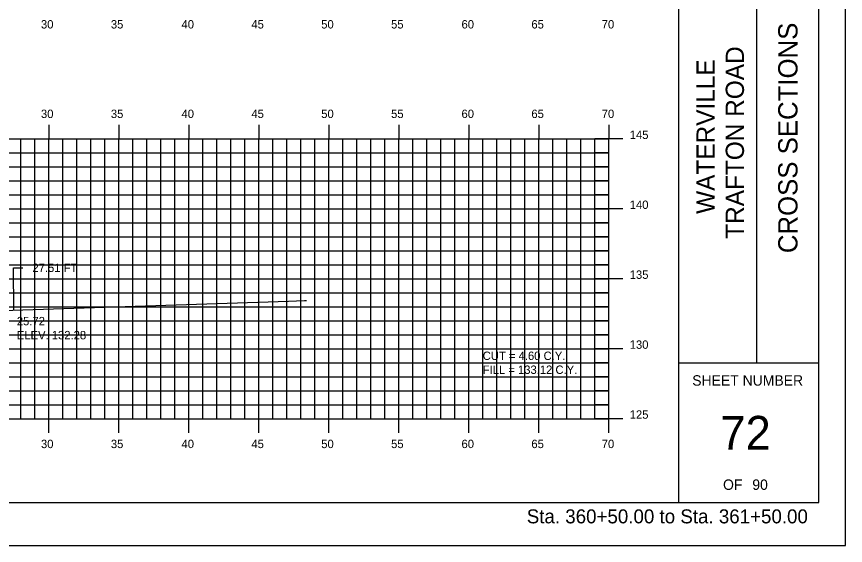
# Model space of a CAD drawing. Extents: x 1146525 to 1146695, y 608981 to 609091.
# Drawn here: x 1146635.4 to 1146694.6, y 608981.3 to 609019.1 of the extents above; entities that cross this region are included whole.
import ezdxf

# ---------------------------------------------------------------- set-up
doc = ezdxf.new("R2010")
doc.units = 0
for name, color, linetype in [('BORDER', 7, 'Continuous'), ('D_Text_Standard', 7, 'Continuous'), ('H_V ANNOTATION', 7, 'Continuous'), ('HIGHWAY_TITLE', 7, 'Continuous'), ('MAJOR', 7, 'Continuous'), ('MINOR', 7, 'Continuous'), ('PLOT BOUNDARY', 7, 'Continuous'), ('S_Roadway_Centerline', 7, 'Continuous')]:
    doc.layers.add(name, color=color, linetype=linetype)

msp = doc.modelspace()

# ---------------------------------------------------------------- linework, layer by layer
at = {"layer": 'BORDER'}
for p, q in [((1146682.671, 608984.335), (1146682.671, 609089.335)), ((1146688.262, 608994.338), (1146688.262, 609029.338)), ((1146682.671, 608994.338), (1146692.671, 608994.338))]:
    msp.add_line(p, q, dxfattribs=at)
msp.add_lwpolyline([(1146532.671, 608984.335), (1146692.671, 608984.335), (1146692.671, 609089.335), (1146532.671, 609089.335)], close=True, dxfattribs=at)
at = {"layer": 'D_Text_Standard'}
msp.add_lwpolyline([(1146635.18, 608998.09), (1146635.15, 609001.127), (1146635.83, 609001.127)], dxfattribs=at)
at = {"layer": 'MAJOR'}
for p, q in [((1146637.671, 609011.337), (1146637.671, 609010.335)), ((1146642.671, 609011.337), (1146642.671, 609010.335)), ((1146647.671, 609011.337), (1146647.671, 609010.335)), ((1146652.671, 609011.337), (1146652.671, 609010.335)), ((1146657.671, 609011.337), (1146657.671, 609010.335)), ((1146662.671, 609011.337), (1146662.671, 609010.335)), ((1146667.671, 609011.337), (1146667.671, 609010.335)), ((1146672.671, 609011.337), (1146672.671, 609010.335)), ((1146677.671, 609011.337), (1146677.671, 609010.335)), ((1146537.671, 609010.335), (1146677.671, 609010.335)), ((1146537.671, 609010.335), (1146677.671, 609010.335)), ((1146637.671, 608990.335), (1146637.671, 609010.335)), ((1146642.671, 608990.335), (1146642.671, 609010.335)), ((1146647.671, 608990.335), (1146647.671, 609010.335)), ((1146652.671, 608990.335), (1146652.671, 609010.335)), ((1146657.671, 608990.335), (1146657.671, 609010.335)), ((1146662.671, 608990.335), (1146662.671, 609010.335)), ((1146667.671, 608990.335), (1146667.671, 609010.335)), ((1146672.671, 608990.335), (1146672.671, 609010.335)), ((1146678.673, 609010.335), (1146676.669, 609010.335)), ((1146677.671, 608990.335), (1146677.671, 609010.335)), ((1146677.671, 608990.335), (1146677.671, 609010.335)), ((1146537.671, 609005.335), (1146677.671, 609005.335)), ((1146678.673, 609005.335), (1146676.669, 609005.335)), ((1146537.671, 609000.335), (1146677.671, 609000.335)), ((1146678.673, 609000.335), (1146676.669, 609000.335)), ((1146537.671, 608995.335), (1146677.671, 608995.335)), ((1146678.673, 608995.335), (1146676.669, 608995.335)), ((1146537.671, 608990.335), (1146677.671, 608990.335)), ((1146537.671, 608990.335), (1146677.671, 608990.335)), ((1146637.671, 608989.333), (1146637.671, 608990.335)), ((1146642.671, 608989.333), (1146642.671, 608990.335)), ((1146647.671, 608989.333), (1146647.671, 608990.335)), ((1146652.671, 608989.333), (1146652.671, 608990.335)), ((1146657.671, 608989.333), (1146657.671, 608990.335)), ((1146662.671, 608989.333), (1146662.671, 608990.335)), ((1146667.671, 608989.333), (1146667.671, 608990.335)), ((1146672.671, 608989.333), (1146672.671, 608990.335)), ((1146678.673, 608990.335), (1146676.669, 608990.335)), ((1146677.671, 608989.333), (1146677.671, 608990.335))]:
    msp.add_line(p, q, dxfattribs=at)
at = {"layer": 'MINOR'}
for p, q in [((1146635.671, 608990.335), (1146635.671, 609010.335)), ((1146636.671, 608990.335), (1146636.671, 609010.335)), ((1146638.671, 608990.335), (1146638.671, 609010.335)), ((1146639.671, 608990.335), (1146639.671, 609010.335)), ((1146640.671, 608990.335), (1146640.671, 609010.335)), ((1146641.671, 608990.335), (1146641.671, 609010.335)), ((1146643.671, 608990.335), (1146643.671, 609010.335)), ((1146644.671, 608990.335), (1146644.671, 609010.335)), ((1146645.671, 608990.335), (1146645.671, 609010.335)), ((1146646.671, 608990.335), (1146646.671, 609010.335)), ((1146648.671, 608990.335), (1146648.671, 609010.335)), ((1146649.671, 608990.335), (1146649.671, 609010.335)), ((1146650.671, 608990.335), (1146650.671, 609010.335)), ((1146651.671, 608990.335), (1146651.671, 609010.335)), ((1146653.671, 608990.335), (1146653.671, 609010.335)), ((1146654.671, 608990.335), (1146654.671, 609010.335)), ((1146655.671, 608990.335), (1146655.671, 609010.335)), ((1146656.671, 608990.335), (1146656.671, 609010.335)), ((1146658.671, 608990.335), (1146658.671, 609010.335)), ((1146659.671, 608990.335), (1146659.671, 609010.335)), ((1146660.671, 608990.335), (1146660.671, 609010.335)), ((1146661.671, 608990.335), (1146661.671, 609010.335)), ((1146663.671, 608990.335), (1146663.671, 609010.335)), ((1146664.671, 608990.335), (1146664.671, 609010.335)), ((1146665.671, 608990.335), (1146665.671, 609010.335)), ((1146666.671, 608990.335), (1146666.671, 609010.335)), ((1146668.671, 608990.335), (1146668.671, 609010.335)), ((1146669.671, 608990.335), (1146669.671, 609010.335)), ((1146670.671, 608990.335), (1146670.671, 609010.335)), ((1146671.671, 608990.335), (1146671.671, 609010.335)), ((1146673.671, 608990.335), (1146673.671, 609010.335)), ((1146674.671, 608990.335), (1146674.671, 609010.335)), ((1146675.671, 608990.335), (1146675.671, 609010.335)), ((1146676.671, 608990.335), (1146676.671, 609010.335)), ((1146537.671, 609009.335), (1146677.671, 609009.335)), ((1146677.671, 609009.335), (1146676.669, 609009.335)), ((1146537.671, 609008.335), (1146677.671, 609008.335)), ((1146677.671, 609008.335), (1146676.669, 609008.335)), ((1146537.671, 609007.335), (1146677.671, 609007.335)), ((1146677.671, 609007.335), (1146676.669, 609007.335)), ((1146537.671, 609006.335), (1146677.671, 609006.335)), ((1146677.671, 609006.335), (1146676.669, 609006.335)), ((1146537.671, 609004.335), (1146677.671, 609004.335)), ((1146677.671, 609004.335), (1146676.669, 609004.335)), ((1146537.671, 609003.335), (1146677.671, 609003.335)), ((1146677.671, 609003.335), (1146676.669, 609003.335)), ((1146537.671, 609002.335), (1146677.671, 609002.335)), ((1146677.671, 609002.335), (1146676.669, 609002.335)), ((1146537.671, 609001.335), (1146677.671, 609001.335)), ((1146677.671, 609001.335), (1146676.669, 609001.335)), ((1146537.671, 608999.335), (1146677.671, 608999.335)), ((1146677.671, 608999.335), (1146676.669, 608999.335)), ((1146537.671, 608998.335), (1146677.671, 608998.335)), ((1146677.671, 608998.335), (1146676.669, 608998.335)), ((1146537.671, 608997.335), (1146677.671, 608997.335)), ((1146677.671, 608997.335), (1146676.669, 608997.335)), ((1146537.671, 608996.335), (1146677.671, 608996.335)), ((1146677.671, 608996.335), (1146676.669, 608996.335)), ((1146537.671, 608994.335), (1146677.671, 608994.335)), ((1146677.671, 608994.335), (1146676.669, 608994.335)), ((1146537.671, 608993.335), (1146677.671, 608993.335)), ((1146677.671, 608993.335), (1146676.669, 608993.335)), ((1146537.671, 608992.335), (1146677.671, 608992.335)), ((1146677.671, 608992.335), (1146676.669, 608992.335)), ((1146537.671, 608991.335), (1146677.671, 608991.335)), ((1146677.671, 608991.335), (1146676.669, 608991.335))]:
    msp.add_line(p, q, dxfattribs=at)
at = {"layer": 'PLOT BOUNDARY'}
msp.add_lwpolyline([(1146524.578, 608981.276), (1146694.578, 608981.276), (1146694.578, 609091.276), (1146524.578, 609091.276)], close=True, dxfattribs=at)
at = {"layer": 'S_Roadway_Centerline'}
msp.add_lwpolyline([(1146558.972, 608999.325), (1146561.084, 608999.24), (1146581.4, 608998.525), (1146588.809, 608997.707), (1146588.862, 608997.698), (1146592.979, 608998.756), (1146592.988, 608998.759), (1146592.993, 608998.758), (1146594.907, 608998.757), (1146601.66, 608998.911), (1146606.094, 608999.07), (1146612.762, 608998.848), (1146617.098, 608998.7), (1146618.903, 608998.533), (1146621.302, 608998.363), (1146623.626, 608997.311), (1146624.919, 608996.889), (1146629.659, 608997.697), (1146630.243, 608997.884), (1146632.151, 608997.991), (1146654.81, 608998.736), (1146655.932, 608998.78), (1146656.093, 608998.782)], dxfattribs=at)

# ---------------------------------------------------------------- texts
at = {"layer": 'BORDER'}
msp.add_text('CROSS SECTIONS', height=1.37787, rotation=90, dxfattribs=at).set_placement((1146691.156, 609002.172))
for s, height, p in [('SHEET NUMBER', 0.74527, (1146683.637, 608992.701)), ('72', 2.4194, (1146685.647, 608988.118)), ('OF', 0.7453, (1146685.838, 608985.248)), ('90', 0.7453, (1146687.928, 608985.248))]:
    msp.add_text(s, height=height, dxfattribs=at).set_placement(p)
at = {"layer": 'D_Text_Standard'}
for s, p in [('27.51 FT', (1146636.51, 609000.827)), ('25.72', (1146635.395, 608997.014)), ('ELEV. 132.28', (1146635.395, 608996.012)), ('CUT = 4.60 C.Y.', (1146668.671, 608994.535)), ('FILL = 133.12 C.Y.', (1146668.671, 608993.539))]:
    msp.add_text(s, height=0.6, dxfattribs=at).set_placement(p)
at = {"layer": 'H_V ANNOTATION'}
for s, height, p in [('30', 0.6, (1146637.12, 609018.235)), ('35', 0.6, (1146642.112, 609018.235)), ('40', 0.6, (1146647.157, 609018.235)), ('45', 0.6, (1146652.149, 609018.235)), ('50', 0.6, (1146657.136, 609018.235)), ('55', 0.6, (1146662.128, 609018.235)), ('60', 0.6, (1146667.157, 609018.235)), ('65', 0.6, (1146672.149, 609018.235)), ('70', 0.6, (1146677.173, 609018.235)), ('30', 0.6, (1146637.12, 609011.835)), ('35', 0.6, (1146642.112, 609011.835)), ('40', 0.6, (1146647.157, 609011.835)), ('45', 0.6, (1146652.149, 609011.835)), ('50', 0.6, (1146657.136, 609011.835)), ('55', 0.6, (1146662.128, 609011.835)), ('60', 0.6, (1146667.157, 609011.835)), ('65', 0.6, (1146672.149, 609011.835)), ('70', 0.6, (1146677.173, 609011.835)), ('145', 0.6, (1146679.171, 609010.335)), ('140', 0.6, (1146679.171, 609005.335)), ('135', 0.6, (1146679.171, 609000.335)), ('130', 0.6, (1146679.171, 608995.335)), ('125', 0.6, (1146679.171, 608990.335)), ('30', 0.6, (1146637.12, 608988.235)), ('35', 0.6, (1146642.112, 608988.235)), ('40', 0.6, (1146647.157, 608988.235)), ('45', 0.6, (1146652.149, 608988.235)), ('50', 0.6, (1146657.136, 608988.235)), ('55', 0.6, (1146662.128, 608988.235)), ('60', 0.6, (1146667.157, 608988.235)), ('65', 0.6, (1146672.149, 608988.235)), ('70', 0.6, (1146677.173, 608988.235)), ('Sta. 360+50.00 to Sta. 361+50.00', 1.0002, (1146671.817, 608982.855))]:
    msp.add_text(s, height=height, dxfattribs=at).set_placement(p)
at = {"layer": 'HIGHWAY_TITLE'}
for s, height, p in [('TRAFTON ROAD', 1.30428, (1146687.331, 609003.201)), ('WATERVILLE', 1.3043, (1146685.244, 609004.98))]:
    msp.add_text(s, height=height, rotation=90, dxfattribs=at).set_placement(p)

doc.saveas('drawing.dxf')
